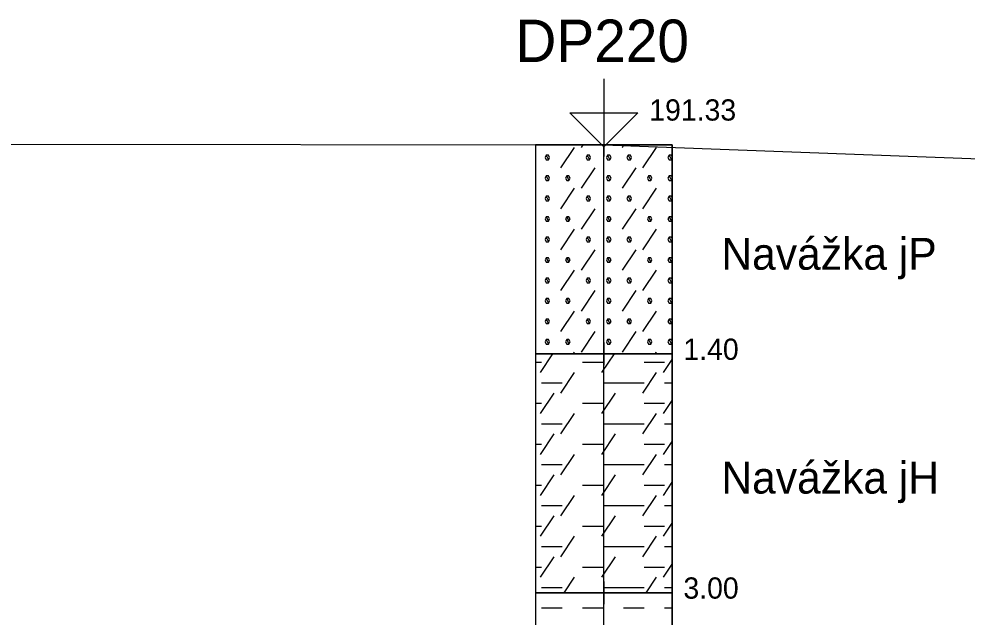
# Model space of a CAD drawing. Extents: x 3042 to 4120, y 576 to 2694.
# Drawn here: x 3936.12 to 3967.88, y 1358.15 to 1378.19 of the extents above; entities that cross this region are included whole.
import ezdxf

# ---------------------------------------------------------------- set-up
doc = ezdxf.new("R2010")
doc.units = 0
for name, color, linetype in [('11', 7, 'Continuous'), ('15', 7, 'Continuous'), ('16', 7, 'Continuous'), ('17', 7, 'Continuous'), ('18', 7, 'Continuous'), ('51', 7, 'Continuous'), ('52', 7, 'Continuous'), ('53', 7, 'Continuous'), ('56', 7, 'Continuous')]:
    doc.layers.add(name, color=color, linetype=linetype)

msp = doc.modelspace()

# ---------------------------------------------------------------- linework, layer by layer
at = {"layer": '11'}
for p, q in [((3882.673, 1374.063), (3955.713, 1373.963)), ((3955.713, 1373.963), (3989.313, 1372.713))]:
    msp.add_line(p, q, dxfattribs=at)
at = {"layer": '15'}
msp.add_lwpolyline([(3955.713, 1376.185), (3955.713, 1373.899), (3954.57, 1375.042), (3956.856, 1375.042), (3955.713, 1373.899)], dxfattribs=at)
at = {"layer": '18'}
msp.add_line((3955.713, 1327.313), (3955.713, 1373.963), dxfattribs=at)
at = {"layer": '51'}
for points in [[(3953.427, 1366.963), (3957.999, 1366.963), (3957.999, 1373.963), (3953.427, 1373.963)], [(3953.427, 1358.963), (3957.999, 1358.963), (3957.999, 1366.963), (3953.427, 1366.963)], [(3953.427, 1344.463), (3957.999, 1344.463), (3957.999, 1358.963), (3953.427, 1358.963)]]:
    msp.add_lwpolyline(points, close=True, dxfattribs=at)
for points in [[(3954.279, 1373.198), (3954.736, 1373.884)], [(3954.965, 1373.884), (3955.017, 1373.963)], [(3956.336, 1373.884), (3956.389, 1373.963)], [(3957.022, 1373.198), (3957.479, 1373.884)], [(3953.784, 1373.617), (3953.745, 1373.541), (3953.784, 1373.465), (3953.86, 1373.465), (3953.898, 1373.541), (3953.86, 1373.617), (3953.784, 1373.617), (3953.86, 1373.465)], [(3955.155, 1373.617), (3955.117, 1373.541), (3955.155, 1373.465), (3955.231, 1373.465), (3955.269, 1373.541), (3955.231, 1373.617), (3955.155, 1373.617), (3955.231, 1373.465)], [(3955.841, 1373.617), (3955.803, 1373.541), (3955.841, 1373.465), (3955.917, 1373.465), (3955.955, 1373.541), (3955.917, 1373.617), (3955.841, 1373.617), (3955.917, 1373.465)], [(3956.527, 1373.617), (3956.489, 1373.541), (3956.527, 1373.465), (3956.603, 1373.465), (3956.641, 1373.541), (3956.603, 1373.617), (3956.527, 1373.617), (3956.603, 1373.465)], [(3957.898, 1373.617), (3957.86, 1373.541), (3957.898, 1373.465), (3957.975, 1373.465), (3957.999, 1373.514)], [(3957.999, 1373.568), (3957.975, 1373.617), (3957.898, 1373.617), (3957.975, 1373.465)], [(3954.965, 1372.512), (3955.422, 1373.198)], [(3956.336, 1372.512), (3956.793, 1373.198)], [(3953.784, 1372.931), (3953.745, 1372.855), (3953.784, 1372.779), (3953.86, 1372.779), (3953.898, 1372.855), (3953.86, 1372.931), (3953.784, 1372.931), (3953.86, 1372.779)], [(3954.469, 1372.931), (3954.431, 1372.855), (3954.469, 1372.779), (3954.546, 1372.779), (3954.584, 1372.855), (3954.546, 1372.931), (3954.469, 1372.931), (3954.546, 1372.779)], [(3955.841, 1372.931), (3955.803, 1372.855), (3955.841, 1372.779), (3955.917, 1372.779), (3955.955, 1372.855), (3955.917, 1372.931), (3955.841, 1372.931), (3955.917, 1372.779)], [(3957.213, 1372.931), (3957.174, 1372.855), (3957.213, 1372.779), (3957.289, 1372.779), (3957.327, 1372.855), (3957.289, 1372.931), (3957.213, 1372.931), (3957.289, 1372.779)], [(3957.898, 1372.931), (3957.86, 1372.855), (3957.898, 1372.779), (3957.975, 1372.779), (3957.999, 1372.828)], [(3957.999, 1372.883), (3957.975, 1372.931), (3957.898, 1372.931), (3957.975, 1372.779)], [(3953.784, 1372.246), (3953.745, 1372.169), (3953.784, 1372.093), (3953.86, 1372.093), (3953.898, 1372.169), (3953.86, 1372.246), (3953.784, 1372.246), (3953.86, 1372.093)], [(3954.279, 1371.827), (3954.736, 1372.512)], [(3955.155, 1372.246), (3955.117, 1372.169), (3955.155, 1372.093), (3955.231, 1372.093), (3955.269, 1372.169), (3955.231, 1372.246), (3955.155, 1372.246), (3955.231, 1372.093)], [(3955.841, 1372.246), (3955.803, 1372.169), (3955.841, 1372.093), (3955.917, 1372.093), (3955.955, 1372.169), (3955.917, 1372.246), (3955.841, 1372.246), (3955.917, 1372.093)], [(3956.527, 1372.246), (3956.489, 1372.169), (3956.527, 1372.093), (3956.603, 1372.093), (3956.641, 1372.169), (3956.603, 1372.246), (3956.527, 1372.246), (3956.603, 1372.093)], [(3957.022, 1371.827), (3957.479, 1372.512)], [(3957.898, 1372.246), (3957.86, 1372.169), (3957.898, 1372.093), (3957.975, 1372.093), (3957.999, 1372.142)], [(3957.999, 1372.197), (3957.975, 1372.246), (3957.898, 1372.246), (3957.975, 1372.093)], [(3954.965, 1371.141), (3955.422, 1371.827)], [(3956.336, 1371.141), (3956.793, 1371.827)], [(3953.784, 1371.56), (3953.745, 1371.484), (3953.784, 1371.407), (3953.86, 1371.407), (3953.898, 1371.484), (3953.86, 1371.56), (3953.784, 1371.56), (3953.86, 1371.407)], [(3954.469, 1371.56), (3954.431, 1371.484), (3954.469, 1371.407), (3954.546, 1371.407), (3954.584, 1371.484), (3954.546, 1371.56), (3954.469, 1371.56), (3954.546, 1371.407)], [(3955.841, 1371.56), (3955.803, 1371.484), (3955.841, 1371.407), (3955.917, 1371.407), (3955.955, 1371.484), (3955.917, 1371.56), (3955.841, 1371.56), (3955.917, 1371.407)], [(3957.213, 1371.56), (3957.174, 1371.484), (3957.213, 1371.407), (3957.289, 1371.407), (3957.327, 1371.484), (3957.289, 1371.56), (3957.213, 1371.56), (3957.289, 1371.407)], [(3957.898, 1371.56), (3957.86, 1371.484), (3957.898, 1371.407), (3957.975, 1371.407), (3957.999, 1371.456)], [(3957.999, 1371.511), (3957.975, 1371.56), (3957.898, 1371.56), (3957.975, 1371.407)], [(3954.279, 1370.455), (3954.736, 1371.141)], [(3957.022, 1370.455), (3957.479, 1371.141)], [(3953.784, 1370.874), (3953.745, 1370.798), (3953.784, 1370.722), (3953.86, 1370.722), (3953.898, 1370.798), (3953.86, 1370.874), (3953.784, 1370.874), (3953.86, 1370.722)], [(3955.155, 1370.874), (3955.117, 1370.798), (3955.155, 1370.722), (3955.231, 1370.722), (3955.269, 1370.798), (3955.231, 1370.874), (3955.155, 1370.874), (3955.231, 1370.722)], [(3955.841, 1370.874), (3955.803, 1370.798), (3955.841, 1370.722), (3955.917, 1370.722), (3955.955, 1370.798), (3955.917, 1370.874), (3955.841, 1370.874), (3955.917, 1370.722)], [(3956.527, 1370.874), (3956.489, 1370.798), (3956.527, 1370.722), (3956.603, 1370.722), (3956.641, 1370.798), (3956.603, 1370.874), (3956.527, 1370.874), (3956.603, 1370.722)], [(3957.898, 1370.874), (3957.86, 1370.798), (3957.898, 1370.722), (3957.975, 1370.722), (3957.999, 1370.77)], [(3957.999, 1370.825), (3957.975, 1370.874), (3957.898, 1370.874), (3957.975, 1370.722)], [(3954.965, 1369.769), (3955.422, 1370.455)], [(3956.336, 1369.769), (3956.793, 1370.455)], [(3953.784, 1370.188), (3953.745, 1370.112), (3953.784, 1370.036), (3953.86, 1370.036), (3953.898, 1370.112), (3953.86, 1370.188), (3953.784, 1370.188), (3953.86, 1370.036)], [(3954.469, 1370.188), (3954.431, 1370.112), (3954.469, 1370.036), (3954.546, 1370.036), (3954.584, 1370.112), (3954.546, 1370.188), (3954.469, 1370.188), (3954.546, 1370.036)], [(3955.841, 1370.188), (3955.803, 1370.112), (3955.841, 1370.036), (3955.917, 1370.036), (3955.955, 1370.112), (3955.917, 1370.188), (3955.841, 1370.188), (3955.917, 1370.036)], [(3957.213, 1370.188), (3957.174, 1370.112), (3957.213, 1370.036), (3957.289, 1370.036), (3957.327, 1370.112), (3957.289, 1370.188), (3957.213, 1370.188), (3957.289, 1370.036)], [(3957.898, 1370.188), (3957.86, 1370.112), (3957.898, 1370.036), (3957.975, 1370.036), (3957.999, 1370.085)], [(3957.999, 1370.139), (3957.975, 1370.188), (3957.898, 1370.188), (3957.975, 1370.036)], [(3954.279, 1369.083), (3954.736, 1369.769)], [(3957.022, 1369.083), (3957.479, 1369.769)], [(3953.784, 1369.502), (3953.745, 1369.426), (3953.784, 1369.35), (3953.86, 1369.35), (3953.898, 1369.426), (3953.86, 1369.502), (3953.784, 1369.502), (3953.86, 1369.35)], [(3955.155, 1369.502), (3955.117, 1369.426), (3955.155, 1369.35), (3955.231, 1369.35), (3955.269, 1369.426), (3955.231, 1369.502), (3955.155, 1369.502), (3955.231, 1369.35)], [(3955.841, 1369.502), (3955.803, 1369.426), (3955.841, 1369.35), (3955.917, 1369.35), (3955.955, 1369.426), (3955.917, 1369.502), (3955.841, 1369.502), (3955.917, 1369.35)], [(3956.527, 1369.502), (3956.489, 1369.426), (3956.527, 1369.35), (3956.603, 1369.35), (3956.641, 1369.426), (3956.603, 1369.502), (3956.527, 1369.502), (3956.603, 1369.35)], [(3957.898, 1369.502), (3957.86, 1369.426), (3957.898, 1369.35), (3957.975, 1369.35), (3957.999, 1369.399)], [(3957.999, 1369.454), (3957.975, 1369.502), (3957.898, 1369.502), (3957.975, 1369.35)], [(3954.965, 1368.398), (3955.422, 1369.083)], [(3956.336, 1368.398), (3956.793, 1369.083)], [(3953.784, 1368.817), (3953.745, 1368.74), (3953.784, 1368.664), (3953.86, 1368.664), (3953.898, 1368.74), (3953.86, 1368.817), (3953.784, 1368.817), (3953.86, 1368.664)], [(3954.469, 1368.817), (3954.431, 1368.74), (3954.469, 1368.664), (3954.546, 1368.664), (3954.584, 1368.74), (3954.546, 1368.817), (3954.469, 1368.817), (3954.546, 1368.664)], [(3955.841, 1368.817), (3955.803, 1368.74), (3955.841, 1368.664), (3955.917, 1368.664), (3955.955, 1368.74), (3955.917, 1368.817), (3955.841, 1368.817), (3955.917, 1368.664)], [(3957.213, 1368.817), (3957.174, 1368.74), (3957.213, 1368.664), (3957.289, 1368.664), (3957.327, 1368.74), (3957.289, 1368.817), (3957.213, 1368.817), (3957.289, 1368.664)], [(3957.898, 1368.817), (3957.86, 1368.74), (3957.898, 1368.664), (3957.975, 1368.664), (3957.999, 1368.713)], [(3957.999, 1368.768), (3957.975, 1368.817), (3957.898, 1368.817), (3957.975, 1368.664)], [(3953.784, 1368.131), (3953.745, 1368.055), (3953.784, 1367.978), (3953.86, 1367.978), (3953.898, 1368.055), (3953.86, 1368.131), (3953.784, 1368.131), (3953.86, 1367.978)], [(3954.279, 1367.712), (3954.736, 1368.398)], [(3955.155, 1368.131), (3955.117, 1368.055), (3955.155, 1367.978), (3955.231, 1367.978), (3955.269, 1368.055), (3955.231, 1368.131), (3955.155, 1368.131), (3955.231, 1367.978)], [(3955.841, 1368.131), (3955.803, 1368.055), (3955.841, 1367.978), (3955.917, 1367.978), (3955.955, 1368.055), (3955.917, 1368.131), (3955.841, 1368.131), (3955.917, 1367.978)], [(3956.527, 1368.131), (3956.489, 1368.055), (3956.527, 1367.978), (3956.603, 1367.978), (3956.641, 1368.055), (3956.603, 1368.131), (3956.527, 1368.131), (3956.603, 1367.978)], [(3957.022, 1367.712), (3957.479, 1368.398)], [(3957.898, 1368.131), (3957.86, 1368.055), (3957.898, 1367.978), (3957.975, 1367.978), (3957.999, 1368.027)], [(3957.999, 1368.082), (3957.975, 1368.131), (3957.898, 1368.131), (3957.975, 1367.978)], [(3954.965, 1367.026), (3955.422, 1367.712)], [(3956.336, 1367.026), (3956.793, 1367.712)], [(3953.784, 1367.445), (3953.745, 1367.369), (3953.784, 1367.293), (3953.86, 1367.293), (3953.898, 1367.369), (3953.86, 1367.445), (3953.784, 1367.445), (3953.86, 1367.293)], [(3954.469, 1367.445), (3954.431, 1367.369), (3954.469, 1367.293), (3954.546, 1367.293), (3954.584, 1367.369), (3954.546, 1367.445), (3954.469, 1367.445), (3954.546, 1367.293)], [(3955.841, 1367.445), (3955.803, 1367.369), (3955.841, 1367.293), (3955.917, 1367.293), (3955.955, 1367.369), (3955.917, 1367.445), (3955.841, 1367.445), (3955.917, 1367.293)], [(3957.213, 1367.445), (3957.174, 1367.369), (3957.213, 1367.293), (3957.289, 1367.293), (3957.327, 1367.369), (3957.289, 1367.445), (3957.213, 1367.445), (3957.289, 1367.293)], [(3957.898, 1367.445), (3957.86, 1367.369), (3957.898, 1367.293), (3957.975, 1367.293), (3957.999, 1367.341)], [(3957.999, 1367.396), (3957.975, 1367.445), (3957.898, 1367.445), (3957.975, 1367.293)], [(3953.593, 1366.34), (3954.008, 1366.963)], [(3954.694, 1366.963), (3954.736, 1367.026)], [(3955.65, 1366.34), (3956.066, 1366.963)], [(3957.437, 1366.963), (3957.479, 1367.026)], [(3953.427, 1366.683), (3953.631, 1366.683)], [(3955.003, 1366.683), (3955.689, 1366.683)], [(3957.06, 1366.683), (3957.746, 1366.683)], [(3957.708, 1366.34), (3957.999, 1366.777)], [(3954.279, 1365.654), (3954.736, 1366.34)], [(3957.022, 1365.654), (3957.479, 1366.34)], [(3953.631, 1365.997), (3954.317, 1365.997)], [(3955.689, 1365.997), (3956.374, 1365.997)], [(3956.374, 1365.997), (3957.06, 1365.997)], [(3957.746, 1365.997), (3957.999, 1365.997)], [(3953.593, 1364.969), (3954.05, 1365.654)], [(3955.65, 1364.969), (3956.108, 1365.654)], [(3953.427, 1365.311), (3953.631, 1365.311)], [(3955.003, 1365.311), (3955.689, 1365.311)], [(3957.06, 1365.311), (3957.746, 1365.311)], [(3957.708, 1364.969), (3957.999, 1365.405)], [(3954.279, 1364.283), (3954.736, 1364.969)], [(3957.022, 1364.283), (3957.479, 1364.969)], [(3953.631, 1364.626), (3954.317, 1364.626)], [(3955.689, 1364.626), (3956.374, 1364.626)], [(3956.374, 1364.626), (3957.06, 1364.626)], [(3957.746, 1364.626), (3957.999, 1364.626)], [(3953.593, 1363.597), (3954.05, 1364.283)], [(3955.65, 1363.597), (3956.108, 1364.283)], [(3957.708, 1363.597), (3957.999, 1364.034)], [(3953.427, 1363.94), (3953.631, 1363.94)], [(3955.003, 1363.94), (3955.689, 1363.94)], [(3957.06, 1363.94), (3957.746, 1363.94)], [(3954.279, 1362.911), (3954.736, 1363.597)], [(3957.022, 1362.911), (3957.479, 1363.597)], [(3953.631, 1363.254), (3954.317, 1363.254)], [(3955.689, 1363.254), (3956.374, 1363.254)], [(3956.374, 1363.254), (3957.06, 1363.254)], [(3957.746, 1363.254), (3957.999, 1363.254)], [(3953.593, 1362.225), (3954.05, 1362.911)], [(3955.65, 1362.225), (3956.108, 1362.911)], [(3953.427, 1362.568), (3953.631, 1362.568)], [(3955.003, 1362.568), (3955.689, 1362.568)], [(3957.06, 1362.568), (3957.746, 1362.568)], [(3957.708, 1362.225), (3957.999, 1362.662)], [(3954.279, 1361.54), (3954.736, 1362.225)], [(3957.022, 1361.54), (3957.479, 1362.225)], [(3953.631, 1361.882), (3954.317, 1361.882)], [(3955.689, 1361.882), (3956.374, 1361.882)], [(3956.374, 1361.882), (3957.06, 1361.882)], [(3957.746, 1361.882), (3957.999, 1361.882)], [(3953.593, 1360.854), (3954.05, 1361.54)], [(3955.65, 1360.854), (3956.108, 1361.54)], [(3953.427, 1361.197), (3953.631, 1361.197)], [(3955.003, 1361.197), (3955.689, 1361.197)], [(3957.06, 1361.197), (3957.746, 1361.197)], [(3957.708, 1360.854), (3957.999, 1361.29)], [(3954.279, 1360.168), (3954.736, 1360.854)], [(3957.022, 1360.168), (3957.479, 1360.854)], [(3953.631, 1360.511), (3954.317, 1360.511)], [(3955.689, 1360.511), (3956.374, 1360.511)], [(3956.374, 1360.511), (3957.06, 1360.511)], [(3957.746, 1360.511), (3957.999, 1360.511)], [(3953.593, 1359.482), (3954.05, 1360.168)], [(3955.65, 1359.482), (3956.108, 1360.168)], [(3957.708, 1359.482), (3957.999, 1359.919)], [(3953.427, 1359.825), (3953.631, 1359.825)], [(3955.003, 1359.825), (3955.689, 1359.825)], [(3957.06, 1359.825), (3957.746, 1359.825)], [(3954.39, 1358.963), (3954.736, 1359.482)], [(3957.133, 1358.963), (3957.479, 1359.482)], [(3953.631, 1359.139), (3954.317, 1359.139)], [(3955.689, 1359.139), (3956.374, 1359.139)], [(3956.374, 1359.139), (3957.06, 1359.139)], [(3957.746, 1359.139), (3957.999, 1359.139)], [(3953.631, 1358.453), (3954.317, 1358.453)], [(3955.003, 1358.453), (3955.689, 1358.453)], [(3956.374, 1358.453), (3957.06, 1358.453)], [(3957.746, 1358.453), (3957.999, 1358.453)]]:
    msp.add_lwpolyline(points, dxfattribs=at)
at = {"layer": '53'}
for points in [[(3953.427, 1373.963), (3957.999, 1373.963)], [(3953.427, 1373.963), (3953.427, 1338.963)], [(3957.999, 1373.963), (3957.999, 1338.963)], [(3953.427, 1366.963), (3957.999, 1366.963)], [(3953.427, 1358.963), (3957.999, 1358.963)]]:
    msp.add_lwpolyline(points, dxfattribs=at)
at = {"layer": '56'}
for points in [[(3955.713, 1374.344), (3955.713, 1373.582)], [(3955.332, 1373.963), (3956.094, 1373.963)], [(3955.713, 1367.344), (3955.713, 1366.582)], [(3955.332, 1366.963), (3956.094, 1366.963)], [(3955.713, 1359.344), (3955.713, 1358.582)], [(3955.332, 1358.963), (3956.094, 1358.963)]]:
    msp.add_lwpolyline(points, dxfattribs=at)

# ---------------------------------------------------------------- texts
at = {"layer": '16'}
msp.add_text('DP220', height=1.4224, dxfattribs=at).set_placement((3952.75, 1376.742))
at = {"layer": '17'}
msp.add_text('191.33', height=0.7112, dxfattribs=at).set_placement((3957.237, 1374.781))
at = {"layer": '52'}
for s, height, p in [('Navážka jP', 1.0668, (3959.65, 1369.785)), ('1.40', 0.7112, (3958.38, 1366.765)), ('Navážka jH', 1.0668, (3959.65, 1362.285)), ('3.00', 0.7112, (3958.38, 1358.765))]:
    msp.add_text(s, height=height, dxfattribs=at).set_placement(p)

doc.saveas('drawing.dxf')
